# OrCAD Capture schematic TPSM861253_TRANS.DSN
size Custom
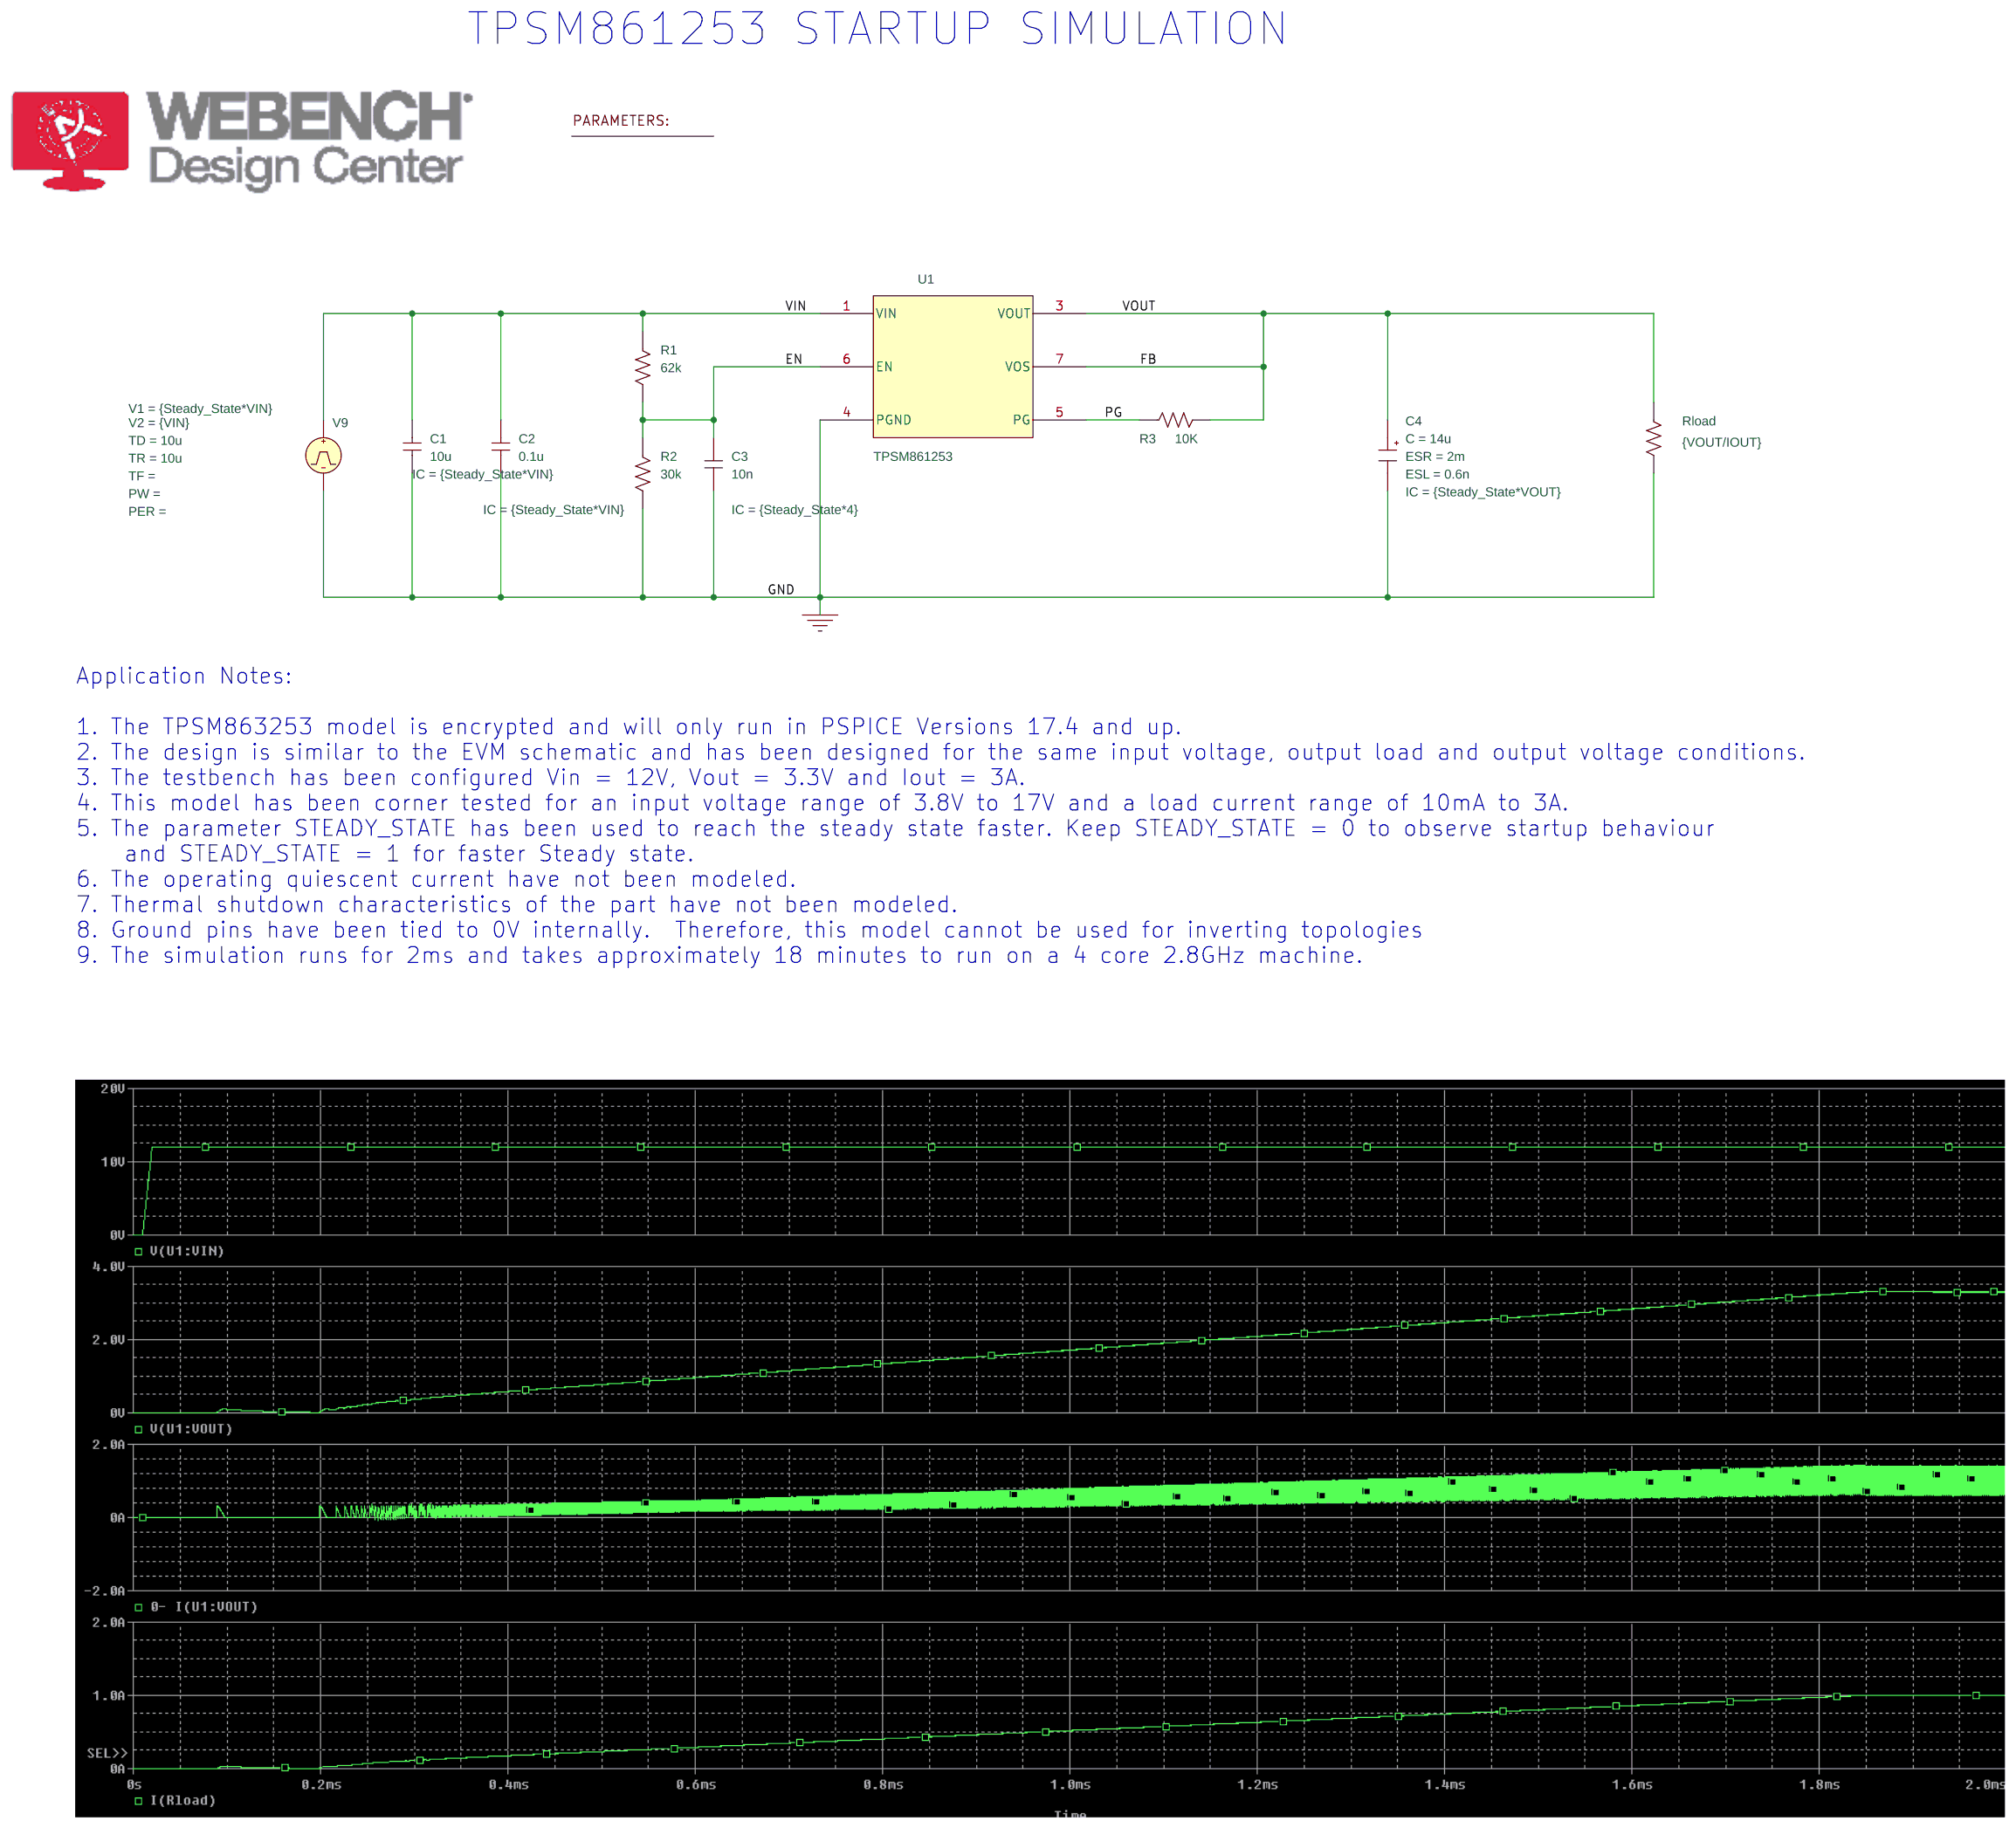
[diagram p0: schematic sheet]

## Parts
3  PARAM
C1  10u  [RAD/CK05]
C2  0.1u  [RAD/CK05]
C3  10n  [RAD/CK05]
C4  CESR
R1  62k  [AX/RC05]
R2  30k  [AX/RC05]
R3  10K  [AX/RC05]
Rload  {VOUT/IOUT}  [AX/RC05]
U1  TPSM861253
V9  VPULSE

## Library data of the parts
3 = PARAM: IOUT: 1; Steady_State: 0; VIN: 12; VOUT: 3.3
C1 C2 = C: IC: {Steady_State*VIN}
C3 = C: IC: {Steady_State*4}
C4 = CESR_0: C: 14u; ESL: 0.6n; ESR: 2m; IC: {Steady_State*VOUT}
R1-R3 Rload = R
U1 = TPSM861253
V9 = VPULSE: TD: 10u; TR: 10u; V1: {Steady_State*VIN}; V2: {VIN}

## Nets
VIN: C1.1 C2.1 R1.1 U1.1(VIN) V9.1(+)
0: C1.2 C2.2 C3.2 C4.2(OUT) R2.2 Rload.2 U1.4(PGND) V9.2(-)
EN: C3.1 R1.2 R2.1 U1.6(EN)
FB: C4.1(IN) R3.2 Rload.1 U1.3(VOUT) U1.7(VOS)
PG: R3.1 U1.5(PG)

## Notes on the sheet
- TPSM861253 STARTUP SIMULATION
- Application Notes:
  1. The TPSM863253 model is encrypted and will only run in PSPICE Versions 17.4 and up.
  2. The design is similar to the EVM schematic and has been designed for the same input voltage, output load and output voltage conditions.
  3. The testbench has been configured Vin = 12V, Vout = 3.3V and Iout = 3A.
  4. This model has been corner tested for an input voltage range of 3.8V to 17V and a load current range of 10mA to 3A.
  5. The parameter STEADY_STATE has been used to reach the steady state faster. Keep STEADY_STATE = 0 to observe startup behaviour
      and STEADY_STATE = 1 for faster Steady state.
  6. The operating quiescent current have not been modeled.
  7. Thermal shutdown characteristics of the part have not been modeled.
  8. Ground pins have been tied to 0V internally.  Therefore, this model cannot be used for inverting topologies
  9. The simulation runs for 2ms and takes approximately 18 minutes to run on a 4 core 2.8GHz machine.
